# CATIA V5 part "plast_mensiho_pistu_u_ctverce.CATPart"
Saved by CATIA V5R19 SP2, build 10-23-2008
Part number: plast_mensiho_pistu_u_ctverce
Bounding box of the stored display mesh (mm): x -67.747 to 67.747, y -75.158 to 174.842, z -67.677 to 67.677
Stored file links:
  C:\Users\Martiin\Desktop\9.semestr\Projekt-diplomka\3D model\plast_mensiho_pistu_u_ctverce.CATPart
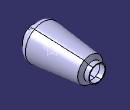
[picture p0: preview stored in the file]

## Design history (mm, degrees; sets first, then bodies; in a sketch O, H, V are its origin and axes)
Body1 (main body)
  Sketch1 on yz-plane, origin (0, 0, 0), H (0, 1, 0), V (0, 0, 1)
    axis line L1 (-94.9763, 0) -> (157.4002, 0)
    point P1 (-94.9763, 0)
    line L2 (-64.1475, 40) -> (-62.9072, 40)
    point P3 (-60.1582, 40)
    line L3 (156.5739, 33) -> (174.8418, 33)
    line L4 (174.8418, 33) -> (174.8418, 30)
    line L5 (-59.9186, 42.7385) -> (-59.396, 48.7116)
    point P7 (-57.5335, 70)
    line L6 (-36.2808, 67.7663) -> (147.6637, 48.4329)
    line L7 (147.6637, 48.4329) -> (156.5739, 33)
    line L8 (-75.1582, 33.4963) -> (-75.1582, 30)
    line L9 (-75.1582, 30) -> (-72.1582, 30)
    line L10 (-72.1582, 30) -> (-72.1582, 34)
    line L11 (-69.1582, 37) -> (-62.9072, 37)
    line L12 (-56.93, 42.4771) -> (-56.4074, 48.4501)
    line L13 (-36.5944, 64.7827) -> (145.8299, 45.6091)
    line L14 (145.8299, 45.6091) -> (154.8418, 30)
    line L15 (174.8418, 30) -> (154.8418, 30)
    point P12 (154.8418, 30)
    arc A1 centre (-38.4759, 46.8813) radius 18 from (-36.5944, 64.7827) to (-56.4074, 48.4501) ccw
    arc A2 centre (-38.4759, 46.8813) radius 21 from (-36.2808, 67.7663) to (-59.396, 48.7116) ccw
    arc A3 centre (-62.9072, 43) radius 3 from (-62.9072, 40) to (-59.9186, 42.7385) ccw
    arc A4 centre (-62.9072, 43) radius 6 from (-62.9072, 37) to (-56.93, 42.4771) ccw
    arc A5 centre (-69.1582, 34) radius 3 from (-69.1582, 37) to (-72.1582, 34) ccw
    line L16 (-64.1475, 40) -> (-75.1582, 40)
    point P30 (-75.1582, 40)
    line L17 (-75.1582, 40) -> (-75.1582, 33.4963)
    distance L2 L1 = 40
    distance P7 L1 = 70
    angle L7 L3 = 120
    distance L8 L4 = 250
    distance P3 L8 = 15
    angle L5 L2 = 95
    angle L6 L3 = 6
    distance L13 L6 = 3
    distance L5 L12 = 3
    distance L14 L7 = 3
    distance L3 L15 = 3
    distance L11 L2 = 3
    distance L10 L8 = 3
    distance L1 L9 = 30
    distance L15 L1 = 30
    radius A1 = 18
    radius A2 = 21
    radius A3 = 3
    radius A4 = 6
    radius A5 = 3
    distance P12 L4 = 20
    coincidence: P1 H, L6 P7, L5 P7, L2 P3, L5 P3, P30 L8
    horizontal: L1 H, L2 H, L3 H, L9 H, L11 H, L15 H
    vertical: L4 V, L8 V, L10 V, L17 V
    tangency: A1 L13, A1 L12, A2 L6, A2 L5, A3 L2, A3 L5, A4 L11, A4 L12, A5 L11, A5 L10, L16 A3
  Shaft1: profile Sketch1, axis Sketch1.L1, angle 360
